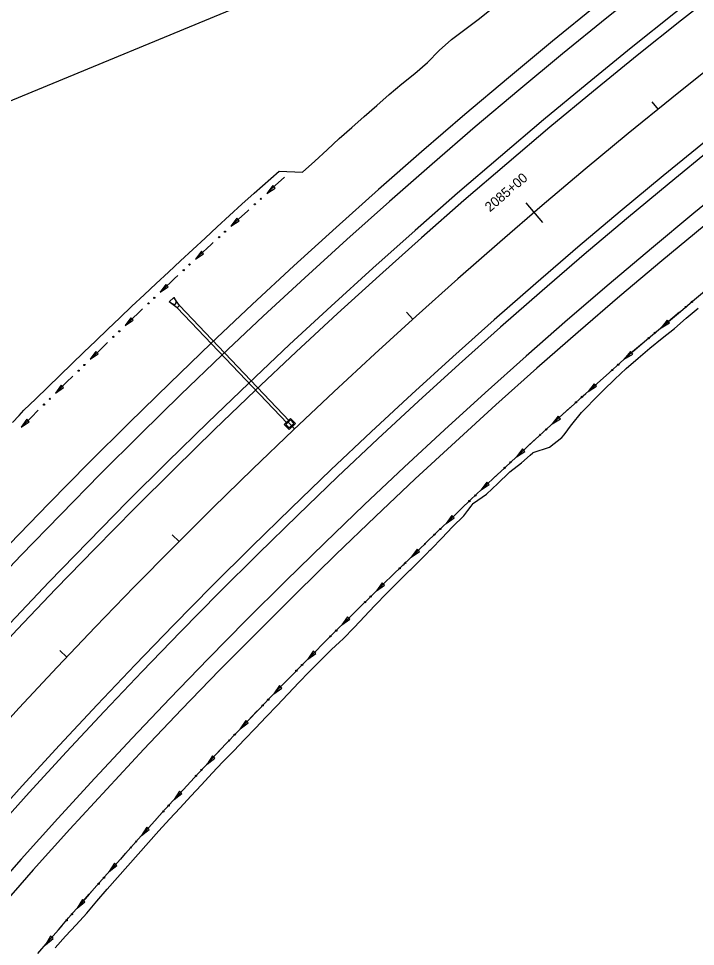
# Model space of a CAD drawing. Extents: x 1611108 to 1749517, y 619561 to 797725.
# Drawn here: x 1714623 to 1715043, y 764673 to 765248 of the extents above; entities that cross this region are included whole.
import ezdxf

# ---------------------------------------------------------------- set-up
doc = ezdxf.new("R2010")
doc.units = 0
for name, color, linetype in [('R_Ditch', 7, 'Continuous'), ('R_Drainage', 7, 'Continuous'), ('R_Horz Alg', 7, 'Continuous'), ('R_Horz Alg Annot', 7, 'Continuous'), ('R_Horz Alg Stationing', 7, 'Continuous'), ('R_Proposed Const Limits', 7, 'Continuous'), ('R_Proposed Road', 7, 'Continuous')]:
    doc.layers.add(name, color=color, linetype=linetype)

msp = doc.modelspace()

# ---------------------------------------------------------------- linework, layer by layer
at = {"layer": 'R_Ditch'}
for p, q in [((1714780.57, 765144.66), (1714776.84, 765139.84)), ((1714780.57, 765144.66), (1714776.84, 765139.84)), ((1714776.84, 765139.84), (1714781.99, 765143.09)), ((1714776.84, 765139.84), (1714781.99, 765143.09)), ((1714781.99, 765143.09), (1714780.57, 765144.66)), ((1714781.99, 765143.09), (1714780.57, 765144.66)), ((1714758.38, 765124.4), (1714754.69, 765119.55)), ((1714758.38, 765124.4), (1714754.69, 765119.55)), ((1714759.81, 765122.84), (1714758.38, 765124.4)), ((1714759.81, 765122.84), (1714758.38, 765124.4)), ((1714754.69, 765119.55), (1714759.81, 765122.84)), ((1714754.69, 765119.55), (1714759.81, 765122.84)), ((1714736.33, 765103.99), (1714732.66, 765099.13)), ((1714736.33, 765103.99), (1714732.66, 765099.13)), ((1714732.66, 765099.13), (1714737.77, 765102.44)), ((1714732.66, 765099.13), (1714737.77, 765102.44)), ((1714737.77, 765102.44), (1714736.33, 765103.99)), ((1714737.77, 765102.44), (1714736.33, 765103.99)), ((1714714.42, 765083.44), (1714710.78, 765078.55)), ((1714714.42, 765083.44), (1714710.78, 765078.55)), ((1714710.78, 765078.55), (1714715.87, 765081.9)), ((1714710.78, 765078.55), (1714715.87, 765081.9)), ((1714715.87, 765081.9), (1714714.42, 765083.44)), ((1714715.87, 765081.9), (1714714.42, 765083.44)), ((1714692.64, 765062.74), (1714689.03, 765057.83)), ((1714692.64, 765062.74), (1714689.03, 765057.83)), ((1714689.03, 765057.83), (1714694.1, 765061.21)), ((1714689.03, 765057.83), (1714694.1, 765061.21)), ((1714694.1, 765061.21), (1714692.64, 765062.74)), ((1714694.1, 765061.21), (1714692.64, 765062.74)), ((1715025.13, 765061.25), (1715021.22, 765056.58)), ((1715026.5, 765059.64), (1715025.13, 765061.25)), ((1715021.22, 765056.58), (1715026.5, 765059.64)), ((1714670.99, 765041.9), (1714667.42, 765036.97)), ((1714670.99, 765041.9), (1714667.42, 765036.97)), ((1714667.42, 765036.97), (1714672.47, 765040.38)), ((1714667.42, 765036.97), (1714672.47, 765040.38)), ((1714672.47, 765040.38), (1714670.99, 765041.9)), ((1714672.47, 765040.38), (1714670.99, 765041.9)), ((1715002.27, 765041.74), (1714998.46, 765036.98)), ((1714998.46, 765036.98), (1715003.67, 765040.14)), ((1715003.67, 765040.14), (1715002.27, 765041.74)), ((1714649.49, 765020.92), (1714645.95, 765015.96)), ((1714649.49, 765020.92), (1714645.95, 765015.96)), ((1714650.97, 765019.41), (1714649.49, 765020.92)), ((1714650.97, 765019.41), (1714649.49, 765020.92)), ((1714979.76, 765021.83), (1714975.99, 765017.05)), ((1714981.17, 765020.26), (1714979.76, 765021.83)), ((1714645.95, 765015.96), (1714650.97, 765019.41)), ((1714645.95, 765015.96), (1714650.97, 765019.41)), ((1714975.99, 765017.05), (1714981.17, 765020.26)), ((1714628.12, 764999.8), (1714624.62, 764994.81)), ((1714628.12, 764999.8), (1714624.62, 764994.81)), ((1714624.62, 764994.81), (1714629.61, 764998.3)), ((1714624.62, 764994.81), (1714629.61, 764998.3)), ((1714629.61, 764998.3), (1714628.12, 764999.8)), ((1714629.61, 764998.3), (1714628.12, 764999.8)), ((1714957.43, 765001.73), (1714953.71, 764996.91)), ((1714953.71, 764996.91), (1714958.86, 765000.16)), ((1714958.86, 765000.16), (1714957.43, 765001.73)), ((1714935.29, 764981.41), (1714931.61, 764976.56)), ((1714936.73, 764979.86), (1714935.29, 764981.41)), ((1714931.61, 764976.56), (1714936.73, 764979.86)), ((1714913.34, 764960.9), (1714909.7, 764956.01)), ((1714909.7, 764956.01), (1714914.79, 764959.36)), ((1714914.79, 764959.36), (1714913.34, 764960.9)), ((1714891.58, 764940.18), (1714887.99, 764935.26)), ((1714893.04, 764938.65), (1714891.58, 764940.18)), ((1714887.99, 764935.26), (1714893.04, 764938.65)), ((1714870.01, 764919.26), (1714866.46, 764914.31)), ((1714866.46, 764914.31), (1714871.49, 764917.75)), ((1714871.49, 764917.75), (1714870.01, 764919.26)), ((1714848.41, 764898.39), (1714844.85, 764893.44)), ((1714844.85, 764893.44), (1714849.88, 764896.88)), ((1714849.88, 764896.88), (1714848.41, 764898.39)), ((1714826.97, 764877.34), (1714823.46, 764872.36)), ((1714828.46, 764875.84), (1714826.97, 764877.34)), ((1714823.46, 764872.36), (1714828.46, 764875.84)), ((1714805.72, 764856.09), (1714802.26, 764851.08)), ((1714802.26, 764851.08), (1714807.23, 764854.6)), ((1714807.23, 764854.6), (1714805.72, 764856.09)), ((1714784.67, 764834.65), (1714781.26, 764829.6)), ((1714781.26, 764829.6), (1714786.19, 764833.17)), ((1714786.19, 764833.17), (1714784.67, 764834.65)), ((1714763.82, 764813.01), (1714760.45, 764807.93)), ((1714760.45, 764807.93), (1714765.36, 764811.55)), ((1714765.36, 764811.55), (1714763.82, 764813.01)), ((1714743.18, 764791.18), (1714739.85, 764786.08)), ((1714744.72, 764789.73), (1714743.18, 764791.18)), ((1714739.85, 764786.08), (1714744.72, 764789.73)), ((1714722.73, 764769.16), (1714719.45, 764764.03)), ((1714719.45, 764764.03), (1714724.29, 764767.73)), ((1714724.29, 764767.73), (1714722.73, 764769.16)), ((1714702.49, 764746.96), (1714699.25, 764741.79)), ((1714699.25, 764741.79), (1714704.06, 764745.54)), ((1714704.06, 764745.54), (1714702.49, 764746.96)), ((1714682.44, 764724.57), (1714679.25, 764719.38)), ((1714679.25, 764719.38), (1714684.03, 764723.17)), ((1714684.03, 764723.17), (1714682.44, 764724.57)), ((1714662.58, 764702.03), (1714659.43, 764696.81)), ((1714659.43, 764696.81), (1714664.18, 764700.63)), ((1714664.18, 764700.63), (1714662.58, 764702.03)), ((1714642.91, 764679.32), (1714639.79, 764674.08)), ((1714639.79, 764674.08), (1714644.51, 764677.94)), ((1714644.51, 764677.94), (1714642.91, 764679.32))]:
    msp.add_line(p, q, dxfattribs=at)
for points in [[(1714787.95, 765149.91), (1714780.31, 765142.99), (1714776.84, 765139.84)], [(1714787.95, 765149.91), (1714780.31, 765142.99), (1714776.84, 765139.84)], [(1714765.73, 765129.7), (1714765.07, 765129.1), (1714757.48, 765122.13), (1714754.69, 765119.55)], [(1714765.73, 765129.7), (1714765.07, 765129.1), (1714757.48, 765122.13), (1714754.69, 765119.55)], [(1714765.76, 765129.73), (1714765.73, 765129.7)], [(1714765.76, 765129.73), (1714765.73, 765129.7)], [(1714743.64, 765109.34), (1714742.33, 765108.13), (1714734.78, 765101.1), (1714732.67, 765099.12)], [(1714743.64, 765109.34), (1714742.33, 765108.13), (1714734.78, 765101.1), (1714732.67, 765099.12)], [(1714743.67, 765109.37), (1714743.64, 765109.34)], [(1714743.67, 765109.37), (1714743.64, 765109.34)], [(1714721.69, 765088.84), (1714719.74, 765087), (1714712.24, 765079.93), (1714710.78, 765078.55)], [(1714721.69, 765088.84), (1714719.74, 765087), (1714712.24, 765079.93), (1714710.78, 765078.55)], [(1714721.72, 765088.87), (1714721.69, 765088.84)], [(1714721.72, 765088.87), (1714721.69, 765088.84)], [(1714635.09, 764668.57), (1714641.4, 764675.95), (1714647.74, 764683.31), (1714654.09, 764690.66), (1714660.46, 764697.99), (1714666.85, 764705.3), (1714673.26, 764712.6), (1714679.69, 764719.88), (1714686.14, 764727.14), (1714692.61, 764734.39), (1714699.1, 764741.62), (1714705.61, 764748.83), (1714712.14, 764756.03), (1714718.69, 764763.2), (1714725.26, 764770.35), (1714731.86, 764777.49), (1714738.47, 764784.6), (1714745.11, 764791.7), (1714751.77, 764798.78), (1714758.45, 764805.83), (1714765.15, 764812.87), (1714771.87, 764819.88), (1714778.62, 764826.88), (1714785.38, 764833.86), (1714789.24, 764837.81), (1714792.17, 764840.81), (1714798.97, 764847.75), (1714805.8, 764854.66), (1714812.65, 764861.56), (1714817.35, 764866.27), (1714819.52, 764868.43), (1714826.41, 764875.29), (1714833.32, 764882.12), (1714835.99, 764884.76), (1714840.25, 764888.94), (1714847.2, 764895.73), (1714850.33, 764898.78), (1714854.17, 764902.5), (1714861.16, 764909.25), (1714861.94, 764910.01), (1714862.49, 764910.54), (1714864.59, 764912.55), (1714866.88, 764914.74), (1714867.94, 764915.76), (1714868.17, 764915.98), (1714872.6, 764920.32), (1714874.56, 764922.23), (1714875.12, 764922.78), (1714875.56, 764923.2), (1714882.09, 764929.55), (1714889.08, 764936.31), (1714896.09, 764943.04), (1714899, 764945.83), (1714901.42, 764948.14), (1714902.98, 764949.62), (1714903.05, 764949.7), (1714903.12, 764949.76), (1714910.17, 764956.45), (1714917.24, 764963.12), (1714924.33, 764969.77), (1714924.79, 764970.2), (1714931.44, 764976.4), (1714936.76, 764981.33), (1714938.39, 764982.84), (1714938.42, 764982.86), (1714938.57, 764983.01), (1714945.73, 764989.6), (1714952.9, 764996.17), (1714954.48, 764997.61), (1714960.09, 765002.71), (1714960.3, 765002.91), (1714967.3, 765009.23), (1714971.63, 765013.14), (1714974.53, 765015.74), (1714981.78, 765022.22), (1714989.05, 765028.68), (1714996.34, 765035.11), (1715003.64, 765041.53), (1715010.97, 765047.93), (1715018.4, 765054.21), (1715025.84, 765060.46), (1715033.3, 765066.7), (1715040.78, 765072.92), (1715048.28, 765079.11)], [(1714699.88, 765068.19), (1714697.28, 765065.72), (1714689.83, 765058.6), (1714689.03, 765057.83)], [(1714699.88, 765068.19), (1714697.28, 765065.72), (1714689.83, 765058.6), (1714689.03, 765057.83)], [(1714699.9, 765068.22), (1714699.88, 765068.19)], [(1714699.9, 765068.22), (1714699.88, 765068.19)], [(1715032.72, 765066.22), (1715025.84, 765060.46), (1715021.22, 765056.58)], [(1715032.75, 765066.24), (1715032.72, 765066.22)], [(1714678.2, 765047.4), (1714674.98, 765044.29), (1714667.57, 765037.11), (1714667.42, 765036.97)], [(1714678.2, 765047.4), (1714674.98, 765044.29), (1714667.57, 765037.11), (1714667.42, 765036.97)], [(1714678.22, 765047.43), (1714678.2, 765047.4)], [(1714678.22, 765047.43), (1714678.2, 765047.4)], [(1715009.75, 765046.86), (1715003.64, 765041.53), (1714998.46, 765036.98)], [(1715009.78, 765046.89), (1715009.75, 765046.86)], [(1714656.66, 765026.47), (1714652.82, 765022.71), (1714645.95, 765015.96)], [(1714656.66, 765026.47), (1714652.82, 765022.71), (1714645.95, 765015.96)], [(1714656.68, 765026.49), (1714656.66, 765026.47)], [(1714656.68, 765026.49), (1714656.66, 765026.47)], [(1714987.19, 765027.03), (1714981.78, 765022.22), (1714975.99, 765017.05)], [(1714987.22, 765027.05), (1714987.19, 765027.03)], [(1714635.25, 765005.39), (1714630.8, 765000.97), (1714624.62, 764994.81)], [(1714635.25, 765005.39), (1714630.8, 765000.97), (1714624.62, 764994.81)], [(1714635.28, 765005.42), (1714635.25, 765005.39)], [(1714635.28, 765005.42), (1714635.25, 765005.39)], [(1714964.82, 765006.99), (1714960.3, 765002.91), (1714960.09, 765002.71), (1714954.48, 764997.61), (1714953.71, 764996.91)], [(1714964.84, 765007.01), (1714964.82, 765006.99)], [(1714942.63, 764986.74), (1714938.57, 764983.01), (1714938.42, 764982.86), (1714938.39, 764982.84), (1714936.76, 764981.33), (1714931.61, 764976.56)], [(1714942.65, 764986.77), (1714942.63, 764986.74)], [(1714920.62, 764966.29), (1714917.24, 764963.12), (1714910.17, 764956.45), (1714909.7, 764956.01)], [(1714920.65, 764966.32), (1714920.62, 764966.29)], [(1714898.81, 764945.64), (1714896.09, 764943.04), (1714889.08, 764936.31), (1714887.99, 764935.25)], [(1714898.84, 764945.67), (1714898.81, 764945.64)], [(1714877.19, 764924.79), (1714875.56, 764923.2), (1714875.12, 764922.78), (1714874.56, 764922.23), (1714872.6, 764920.32), (1714868.17, 764915.98), (1714867.94, 764915.76), (1714866.88, 764914.74), (1714866.44, 764914.33)], [(1714877.22, 764924.82), (1714877.19, 764924.79)], [(1714855.61, 764903.89), (1714854.17, 764902.5), (1714850.33, 764898.78), (1714847.2, 764895.73), (1714844.85, 764893.44)], [(1714855.64, 764903.92), (1714855.61, 764903.89)], [(1714834.12, 764882.91), (1714833.32, 764882.12), (1714826.41, 764875.29), (1714823.46, 764872.36)], [(1714834.14, 764882.94), (1714834.12, 764882.91)], [(1714812.82, 764861.73), (1714812.65, 764861.56), (1714805.8, 764854.66), (1714802.26, 764851.08)], [(1714812.85, 764861.76), (1714812.82, 764861.73)], [(1714791.72, 764840.35), (1714789.24, 764837.81), (1714785.38, 764833.86), (1714781.26, 764829.6)], [(1714791.74, 764840.38), (1714791.72, 764840.35)], [(1714770.81, 764818.78), (1714765.15, 764812.87), (1714760.45, 764807.93)], [(1714770.84, 764818.81), (1714770.81, 764818.78)], [(1714750.11, 764797.01), (1714745.11, 764791.7), (1714739.85, 764786.08)], [(1714750.14, 764797.04), (1714750.11, 764797.02)], [(1714729.61, 764775.06), (1714725.26, 764770.35), (1714719.45, 764764.03)], [(1714729.64, 764775.09), (1714729.61, 764775.06)], [(1714709.31, 764752.92), (1714705.61, 764748.83), (1714699.25, 764741.79)], [(1714709.34, 764752.95), (1714709.32, 764752.92)], [(1714689.22, 764730.59), (1714686.14, 764727.14), (1714679.69, 764719.88), (1714679.25, 764719.38)], [(1714689.24, 764730.62), (1714689.22, 764730.59)], [(1714669.31, 764708.1), (1714666.85, 764705.3), (1714660.46, 764697.99), (1714659.43, 764696.81)], [(1714669.33, 764708.13), (1714669.31, 764708.1)], [(1714649.58, 764685.45), (1714647.74, 764683.31), (1714641.4, 764675.95), (1714639.8, 764674.08)], [(1714649.61, 764685.48), (1714649.58, 764685.45)]]:
    msp.add_lwpolyline(points, dxfattribs=at)
for centre in [(1714773.16, 765136.44), (1714773.16, 765136.44), (1714769.46, 765133.06), (1714769.46, 765133.06), (1714747.35, 765112.73), (1714747.35, 765112.73), (1714751.03, 765116.13), (1714751.03, 765116.13), (1714729.03, 765095.68), (1714729.03, 765095.68), (1714725.38, 765092.25), (1714725.38, 765092.25), (1714707.17, 765075.08), (1714707.17, 765075.08), (1715040.46, 765072.6), (1714703.54, 765071.63), (1714703.54, 765071.63), (1715036.6, 765069.4), (1714681.84, 765050.86), (1714681.84, 765050.86), (1714685.45, 765054.33), (1714685.45, 765054.33), (1715013.59, 765050.1), (1715017.42, 765053.33), (1714663.86, 765033.45), (1714663.86, 765033.45), (1714994.73, 765033.65), (1714660.27, 765029.95), (1714660.27, 765029.95), (1714990.97, 765030.33), (1714638.85, 765008.9), (1714638.85, 765008.9), (1714642.41, 765012.42), (1714642.41, 765012.42), (1714968.57, 765010.33), (1714972.29, 765013.68), (1714950.04, 764993.5), (1714946.34, 764990.12), (1714924.31, 764969.7), (1714927.97, 764973.12), (1714906.1, 764952.54), (1714902.47, 764949.08), (1714880.81, 764928.26), (1714884.41, 764931.75), (1714859.25, 764907.36), (1714862.86, 764910.83), (1714841.3, 764889.91), (1714837.72, 764886.41), (1714816.39, 764865.26), (1714819.94, 764868.8), (1714795.26, 764843.91), (1714798.77, 764847.49), (1714777.8, 764825.98), (1714774.32, 764822.37), (1714757.03, 764804.28), (1714753.59, 764800.64), (1714733.05, 764778.72), (1714736.46, 764782.39), (1714712.72, 764756.61), (1714716.1, 764760.31), (1714692.59, 764734.31), (1714695.94, 764738.04), (1714675.97, 764715.61), (1714672.65, 764711.85), (1714656.18, 764693.01), (1714652.89, 764689.22)]:
    msp.add_circle(centre, 0.375, dxfattribs=at)
at = {"layer": 'R_Drainage'}
for p, q in [((1714719.36, 765075.34), (1714716.46, 765072.58)), ((1714721.4, 765068.84), (1714716.46, 765072.58)), ((1714716.46, 765072.58), (1714719.04, 765071.17)), ((1714722.85, 765070.22), (1714719.36, 765075.34)), ((1714719.36, 765075.34), (1714720.64, 765072.7)), ((1714722.85, 765070.22), (1714721.4, 765068.84)), ((1714789.43, 764997.32), (1714721.4, 765068.84)), ((1714790.88, 764998.7), (1714722.85, 765070.22))]:
    msp.add_line(p, q, dxfattribs=at)
for points in [[(1714794.61, 764997.19), (1714791.62, 765000.33), (1714787.76, 764996.65), (1714790.75, 764993.51)], [(1714793.67, 764997.21), (1714791.6, 764999.39), (1714788.7, 764996.63), (1714790.77, 764994.46)]]:
    msp.add_lwpolyline(points, close=True, dxfattribs=at)
msp.add_arc((1714719.6, 765072.18), 1.17, 241.09517, 26.03533, dxfattribs=at)
at = {"layer": 'R_Horz Alg'}
msp.add_arc((1717426.61, 762226.09), 3819.72, 112.5, 179.5, dxfattribs=at)
at = {"layer": 'R_Horz Alg Annot'}
msp.add_line((1713629.09, 764787.55), (1715964.86, 765755.05), dxfattribs=at)
at = {"layer": 'R_Horz Alg Stationing'}
for points in [[(1715015.62, 765196.49), (1715019.4, 765191.83)], [(1714937.39, 765133.88), (1714947.79, 765121.73)], [(1714863.46, 765066.24), (1714867.48, 765061.79)], [(1714790, 764998.17), (1714794.13, 764993.82)], [(1714718.33, 764928.2), (1714722.58, 764923.97)], [(1714648.53, 764856.38), (1714652.89, 764852.26)]]:
    msp.add_lwpolyline(points, dxfattribs=at)
at = {"layer": 'R_Proposed Const Limits'}
for points in [[(1714799.04, 765152.99), (1714806.71, 765159.87), (1714814.28, 765166.85), (1714821.85, 765173.84), (1714829.52, 765180.71), (1714837.26, 765187.5), (1714845.04, 765194.25), (1714852.79, 765201.03), (1714860.69, 765207.64), (1714868.62, 765214.22), (1714876.41, 765220.95), (1714883.64, 765228.35), (1714891.33, 765235.21), (1714899.63, 765241.33), (1714907.88, 765247.52), (1714915.88, 765254.02)], [(1714619.35, 764997.78), (1714623.34, 765002.1), (1714626.33, 765005.41), (1714633.82, 765012.53), (1714641.25, 765019.7), (1714648.66, 765026.9), (1714656.07, 765034.09), (1714663.47, 765041.29), (1714670.87, 765048.5), (1714678.34, 765055.63), (1714685.84, 765062.73), (1714693.35, 765069.82), (1714700.88, 765076.88), (1714708.43, 765083.93), (1714715.93, 765091.02), (1714723.44, 765098.11), (1714731.02, 765105.13), (1714738.61, 765112.12), (1714746.2, 765119.13), (1714753.81, 765126.1), (1714761.44, 765133.05), (1714769.09, 765139.99), (1714784.57, 765153.65), (1714799.04, 765152.99)], [(1714645.74, 764672.13), (1714652.18, 764679.38), (1714658.82, 764686.45), (1714665.26, 764693.7), (1714671.57, 764701.06), (1714677.9, 764708.41), (1714684.28, 764715.71), (1714690.69, 764722.99), (1714697.11, 764730.26), (1714703.55, 764737.52), (1714710.08, 764744.68), (1714716.64, 764751.83), (1714723.2, 764758.97), (1714729.77, 764766.11), (1714736.37, 764773.22), (1714742.98, 764780.31), (1714749.66, 764787.35), (1714756.41, 764794.31), (1714763.15, 764801.29), (1714769.93, 764808.22), (1714776.58, 764815.28), (1714783.25, 764822.33), (1714789.95, 764829.35), (1714793.75, 764833.34), (1714796.65, 764836.37), (1714803.37, 764843.36), (1714810.11, 764850.34), (1714817.03, 764857.14), (1714821.89, 764861.68), (1714824.13, 764863.76), (1714830.95, 764870.66), (1714837.61, 764877.73), (1714840.18, 764880.45), (1714844.29, 764884.77), (1714851.04, 764891.75), (1714854.13, 764894.83), (1714857.92, 764898.6), (1714864.8, 764905.44), (1714865.58, 764906.2), (1714866.12, 764906.74), (1714868.18, 764908.79), (1714870.45, 764911), (1714871.5, 764912), (1714871.74, 764912.23), (1714876.1, 764916.62), (1714878.04, 764918.56), (1714878.59, 764919.11), (1714879.02, 764919.54), (1714885.32, 764926.12), (1714891.98, 764933.2), (1714898.97, 764939.95), (1714901.43, 764943.2), (1714903.5, 764945.9), (1714904.84, 764947.61), (1714904.91, 764947.69), (1714904.97, 764947.76), (1714913.04, 764953.34), (1714920.03, 764960.08), (1714927.08, 764966.76), (1714927.58, 764967.15), (1714934.74, 764972.77), (1714940.19, 764977.53), (1714941.83, 764979.03), (1714941.85, 764979.06), (1714942.02, 764979.2), (1714952.08, 764982.52), (1714959.8, 764988.44), (1714961.12, 764990.17), (1714965.72, 764996.37), (1714965.89, 764996.62), (1714971.87, 765004.06), (1714976, 765008.18), (1714978.76, 765010.92), (1714985.67, 765017.77), (1714992.6, 765024.59), (1714999.61, 765031.33), (1715007.01, 765037.62), (1715014.39, 765043.93), (1715022.01, 765049.97), (1715029.54, 765056.1), (1715036.83, 765062.51), (1715044.34, 765068.67)]]:
    msp.add_lwpolyline(points, dxfattribs=at)
at = {"layer": 'R_Proposed Road'}
for radius in [3893.72, 3883.72, 3859.72, 3853.72, 3785.72, 3779.72, 3755.72, 3745.72]:
    msp.add_arc((1717426.61, 762226.09), radius, 112.5, 179.5, dxfattribs=at)

# ---------------------------------------------------------------- texts
at = {"layer": 'R_Horz Alg Stationing'}
msp.add_text('2085+00', height=6, rotation=40.56525, dxfattribs=at).set_placement((1714915.2, 765128.05))

doc.saveas('drawing.dxf')
